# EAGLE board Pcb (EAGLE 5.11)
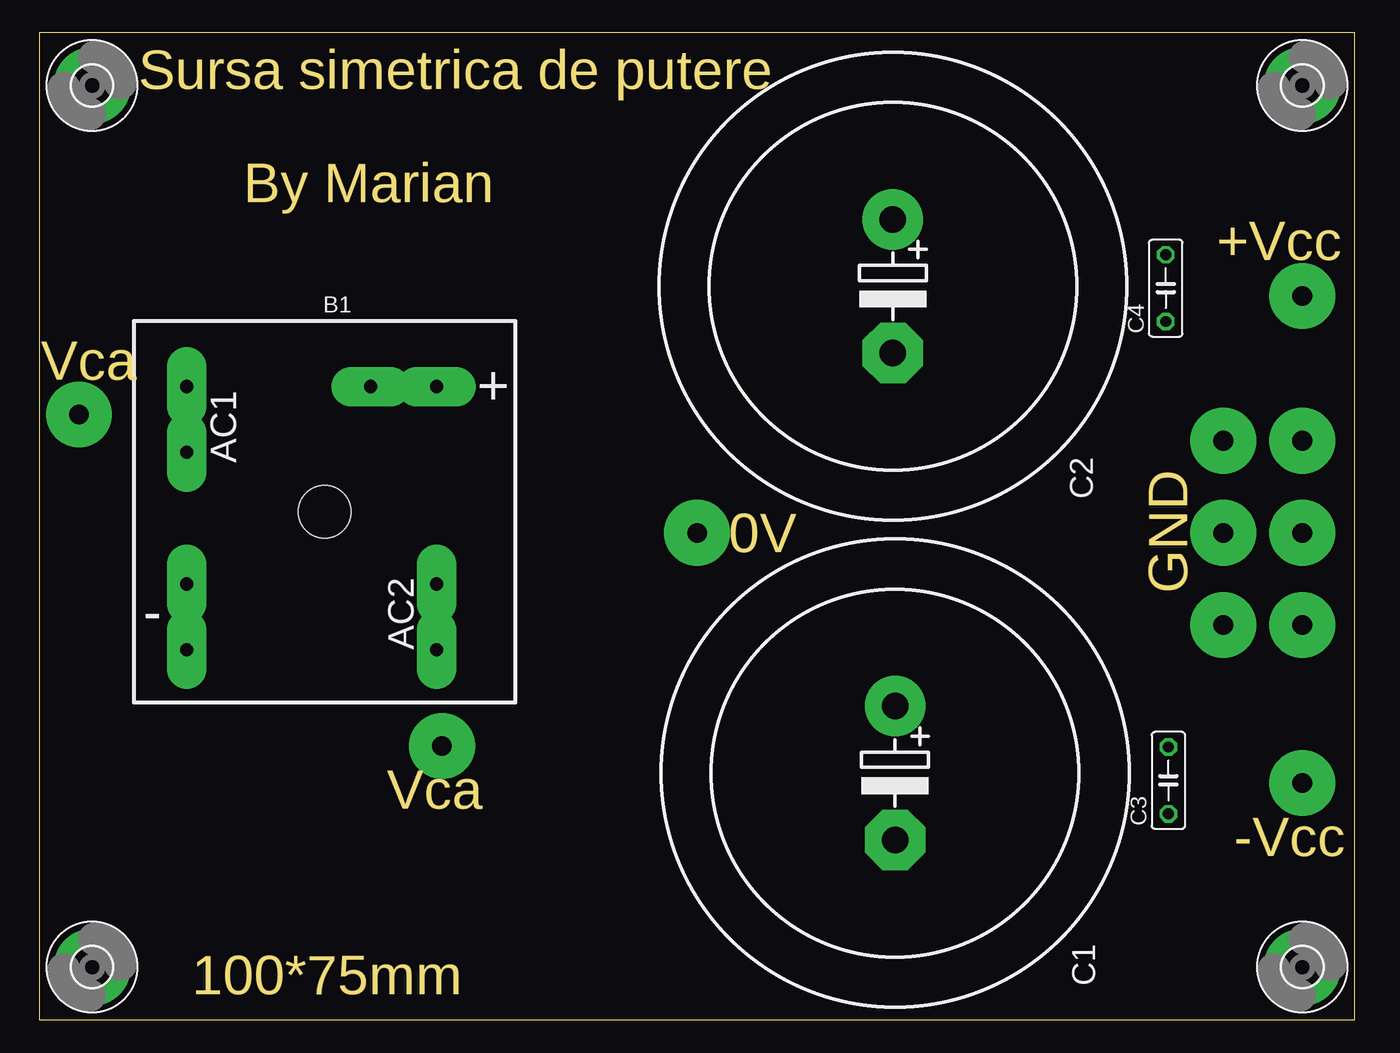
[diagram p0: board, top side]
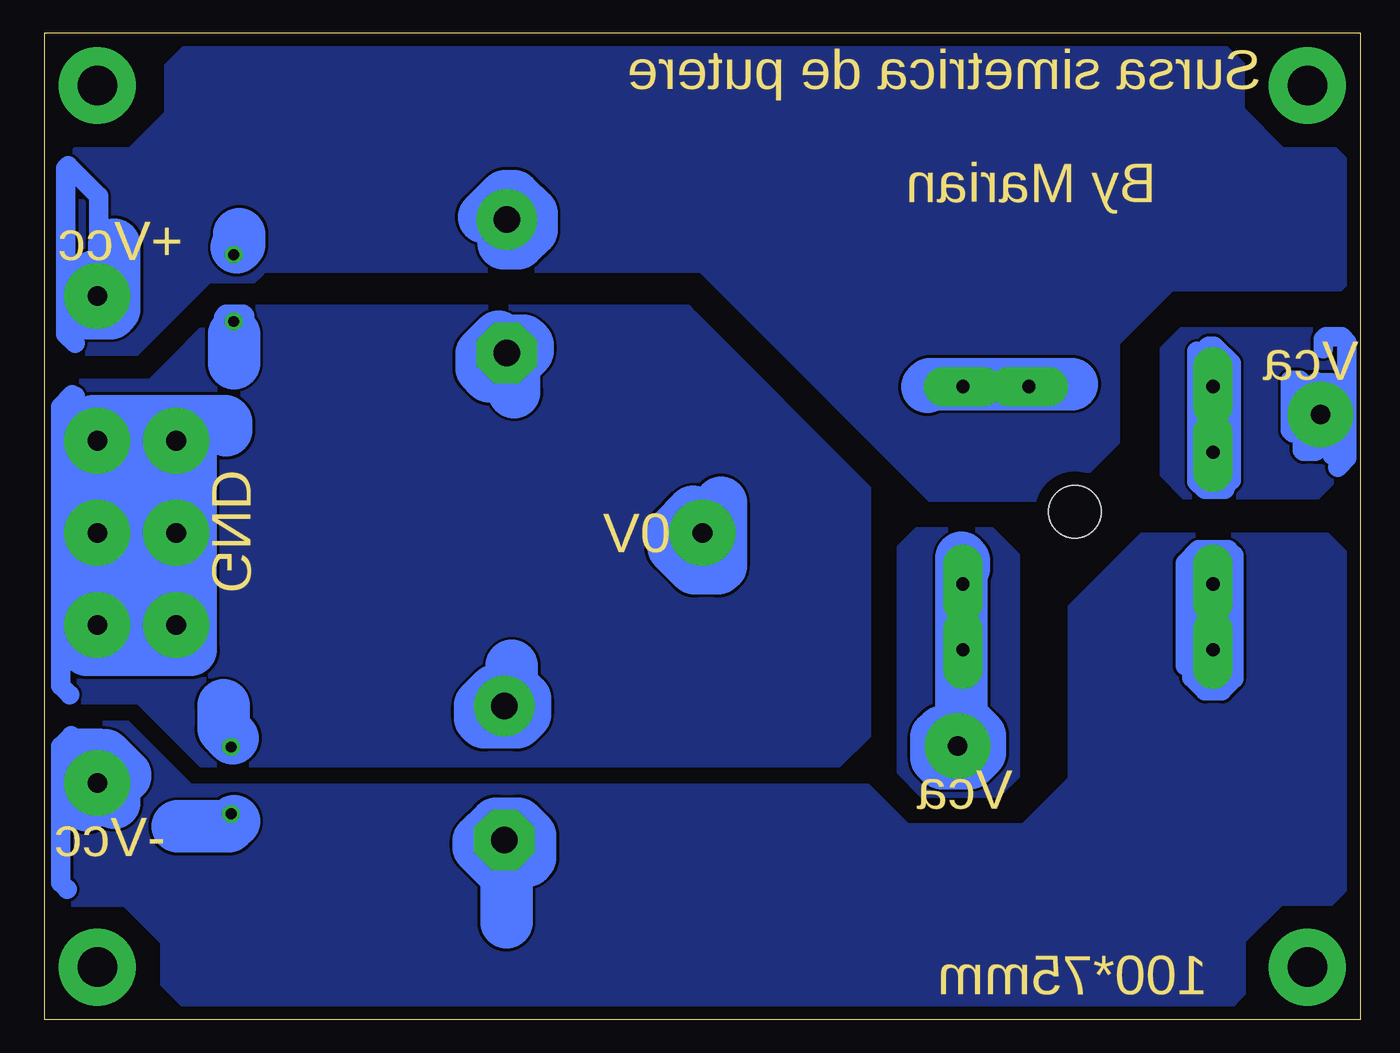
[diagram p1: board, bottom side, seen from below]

Size 100 x 75 mm. Coordinates in mm from the lower left corner, seen from the top.
Outline: 0,0 100,0 100,75 0,75 0,0
Copper layers (1*16): Top 0.035mm / dielectric 1.5mm / Bottom 0.035mm
Design rules "default": minimum track width 10mil, minimum drill 24mil, track to track 8mil, track to pad 8mil, pad to pad 8mil, via to via 8mil, smd to smd 8mil, copper to edge 40mil, drill to drill 8mil, minimum pad ring 10mil, minimum via ring 8mil, stop-mask expansion 4mil, vias tented up to drill 0mil, thermal gap 10mil

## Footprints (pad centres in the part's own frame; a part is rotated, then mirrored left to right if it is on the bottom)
KBPC25 = drill 1 pad 3 long: + 9,2; - -10,-13; AC1 -10,2; AC2 9,-18; P$2 4,2; P$3 -10,-3; P$4 9,2; P$7 9,-13; P$8 9,-13; P$9 -10,-18; P$10 -10,-13 | hole 4: 0.5,-7.5
EB35D = drill 2.007 pad 4.597 round: + -5.08,0 | drill 2.007 pad 4.597 octagon: - 5.08,0
C050-025X075 = drill 0.813 octagon: 1 -2.54,0; 2 2.54,0
3,0-PAD = drill 3 pad 5.842 round: B3,0 0,0

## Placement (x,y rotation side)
B1  25A  [KBPC25]  21.18,46.12 0 top
C1  22m  [EB35D]  65.05,18.75 270 top
C2  22m  [EB35D]  64.88,55.75 270 top
C3  100n  [C050-025X075]  85.83,18.19 90 top
C4  100n  [C050-025X075]  85.63,55.6 90 top
E$1  [3,0-PAD]  4,71 0 top
E$2  [3,0-PAD]  4,4 0 top
E$3  [3,0-PAD]  96,4 0 top
E$4  [3,0-PAD]  96,71 0 top

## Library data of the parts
B1 = KBPC2510
C1-C4 = resistor
E$1-E$4 = holes

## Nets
N$1: B1.AC2
N$2: B1.AC1

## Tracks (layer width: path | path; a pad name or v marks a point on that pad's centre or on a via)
+
  pour Bottom: 18.5,51.4 14.3,55.6 1.5,55.6 0.7,56.4 0.7,64.9 1.9,66.1 5.9,66.1 9,69.2 9,72.6 10.7,74.3 88.9,74.3 90.7,72.5 90.7,68.9 93.5,66.1 97.7,66.1 99.2,64.6 99.2,52.2 97.7,50.7 93,50.7 87.5,56.2 84.1,56.2 83.7,56.6 83.3,57 50.1,57 32.7,39.6 22.8,39.6 18.5,43.9 18.5,48.1
-
  pour Bottom: 2.5,36.8 0.5,34.8 0.5,10.6 2.2,8.9 6,8.9 8.9,6 8.9,2 10.1,0.8 89.1,0.8 91,2.7 91,5.9 93.9,8.8 97.9,8.8 99.2,10.1 99.2,21.1 97.8,22.5 93.7,22.5 88.9,17.7 37.4,17.7 34.4,14.7 25.6,14.7 22,18.3 22,31.4 16.6,36.8 8.6,36.8
AC1
  pour Bottom: 0.4,46.5 0.4,42.6 3.2,39.8 13.4,39.8 15,41.4 15,51 13.6,52.4 1.3,52.4 0.4,51.5
AC2
  pour Bottom: 30.1,17.1 33.3,17.1 35,18.8 35,35.9 33.7,37.2 28,37.2 26.1,35.3 26.1,18.5 27.4,17.2 27.5,17.1
GND
  pour Bottom: 37.4,40.4 50.5,53.5 50.9,53.9 51.1,54.1 86.4,54.1 92,48.5 97.6,48.5 99.2,46.9 99.2,25.1 98.3,24.2 92.9,24.2 88.1,19.4 39.6,19.4 37.4,21.6 37.4,30.5
S$1  (via drill 1.5 pad 5)
  other vias: 3,46 96,55 96,18 96,37 96,44 96,30 90,37 90,30 90,44
S$2  (via drill 1.5 pad 5)
  other vias: 30.6,20.8
S$3  (via drill 1.5 pad 5)
  other vias: 50,37
S$4
  Bottom 1.5: 12.4,50.8 12.4,40.9 11.8,40.3 10.3,40.3 10.3,40.5 9.8,41 9.8,49.9 11.1,51.2 11.5,51.2 11.6,51.1 11.6,41.8 11.2,41.4 11.2,49.7 11,49.9
S$5
  Bottom 1.5: 2.8,51 2.8,51.7 2.6,51.9 1.4,51.9 1,51.5 1,42.7 1.7,42
S$6
  Bottom 1.5: 2.1,42.9 2.1,48.3 2.2,48.4 3.2,48.4 3.3,48.5 3.3,43.3 3.4,43.2 4.3,43.2 4.4,43.3 4.4,48.4 4.6,48.6 5.3,48.6 5.3,44.8 5.1,44.6
S$7
  Bottom 1.5: 13.3,26.9 13.3,34.7 12.3,35.7 10,35.7 9.6,35.3 9.6,25.9 10.5,25 11.8,25 12.8,26 12.8,30.8 12.7,30.9
S$8
  Bottom 1.5: 11.1,26.3 11.1,34.8 12.1,34.8 12.2,34.7 12.2,26.4 11.9,26.1
S$9
  Bottom 4: 21.9,48.3 32.7,48.3 32.9,48.1
S$10
  Bottom 4: 30.1,34.3 30.1,34.9 30.3,35.1 30.3,23 28.9,21.6 28.9,20.3 29.7,19.5 31.8,19.5 32.2,19.9 32.2,21.5 31.8,21.9
S$11
  Bottom 4: 48.6,39.3 48.6,34.5 48.8,34.3 50.6,34.3 52.2,35.9 52.2,37.1 50.7,38.6
S$12
  Bottom 4: 64.3,47.7 64.3,51.6 63.6,51.6 63.3,51.3 63.3,50.8 65.2,48.9 66.2,48.9 66.8,49.5 66.8,50.6 65.5,51.9
S$13
  Bottom 4: 65.1,59 64,59 63,60 63,61.3 64.3,62.6 65,62.6 66.6,61
S$14
  Bottom 4: 85.2,59.7 85.2,58.9 85.4,58.7
S$15
  Bottom 1.5: 85.6,52.1 85.6,52.6 86.4,53.4 86.2,53.6 84.9,53.6 84.8,53.5
  Bottom 4: 85.6,49.9 85.6,52.1
S$16
  Bottom 1.5: 95.9,58.1 95.9,62.6 98.2,64.9 98.4,64.7 98.4,52.1 97.7,51.4
S$17
  Bottom 4: 94.7,58.9 94.7,54 95,53.7 96.7,53.7 96.8,53.8 96.8,55.9 96.2,56.5
S$18
  Bottom 1.5: 97.7,47.4 97.8,47.4 97.9,47.5 98.8,46.6 98.8,25.4 98.1,24.7
S$19
  Bottom 1.5: 95.8,21.4 97.8,21.4 98,21.6 98.8,20.8 98.8,10.4 98.3,9.9
S$20
  Bottom 4: 86.2,44.8 86.2,45.4 86.3,45.5 96.3,45.5 96.8,45 96.8,28.1 88.9,28.1 88.9,43.8 91.2,43.8 | 91.2,43.8 93.4,43.8 93.7,43.5 93.7,30.2 93.8,30.1 92,30.1 91.5,30.6 91.5,43.5 91.2,43.8
S$21
  Bottom 4: 94.7,16.5 94.7,17.7 93.9,18.5 93.9,18.6 95.4,20.1 96.6,20.1 96.9,19.8 96.9,16.4 96.8,16.3
S$22
  Bottom 4: 89.9,14.7 86,14.7 85.6,15.1
S$23
  Bottom 4: 86.4,23.9 86.4,22.1 85.7,21.4
S$24
  Bottom 4: 64.9,7.4 64.9,11 67,13.1 67,13.6 65.7,14.9 64,14.9 63.1,14 63.1,12.3 63.3,12.1
S$25
  Bottom 4: 64.5,26.9 64.5,25.4 63.5,24.4 63.5,23.2 64.1,22.6 66.6,22.6 66.9,22.9 66.9,23.9 65.8,25

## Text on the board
Dimension: Sursa simetrica de putere | By Marian | +Vcc | Vca | 0V | GND | Vca | -Vcc | 100*75mm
